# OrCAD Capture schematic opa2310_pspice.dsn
size A
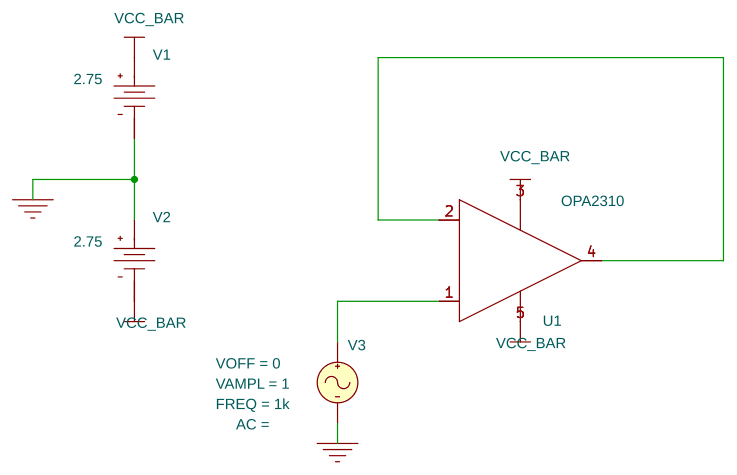
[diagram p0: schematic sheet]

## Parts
U1  OPA2310
V1  VDC
V2  VDC
V3  VSIN

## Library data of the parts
U1 = OPA2310
V1 V2 = VDC: DC: 2.75
V3 = VSIN: FREQ: 1k; VAMPL: 1; VOFF: 0

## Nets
VCC: U1.5(V+) V1.0(+)
VEE: U1.3(V-) V2.1(-)
0: V1.1(-) V2.0(+) V3.2(-)
N00634: U1.2(-) U1.4(OUT)
N00772: U1.1(+) V3.1(+)
